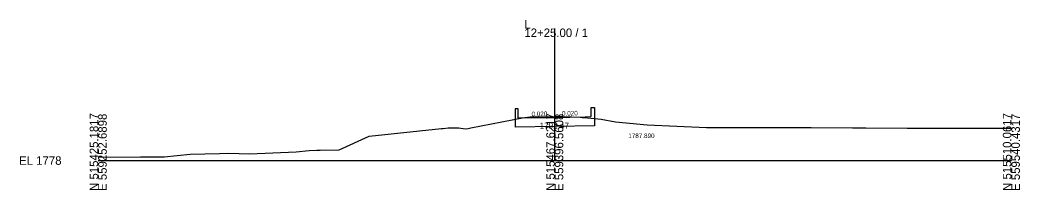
# Model space of a CAD drawing. Extents: x -26 to 1303, y -10 to 9545.
# Drawn here: x -25.7 to 302.8, y 5490.3 to 5546.2 of the extents above; entities that cross this region are included whole.
import ezdxf

# ---------------------------------------------------------------- set-up
doc = ezdxf.new("R2010")
doc.units = 0
for name, color, linetype in [('Exist Cross Section Cell', 7, 'Continuous'), ('Exist XS Center Line Elevation Label', 7, 'Continuous'), ('Exist XS Ground Line', 7, 'Continuous'), ('Prop XS Bridge', 7, 'Continuous'), ('Prop XS Ditch Standard Text', 7, 'Continuous'), ('Prop XS Dump Level', 7, 'Continuous'), ('Prop XS SE Text', 7, 'Continuous')]:
    doc.layers.add(name, color=color, linetype=linetype)

msp = doc.modelspace()

# ---------------------------------------------------------------- linework, layer by layer
at = {"layer": 'Exist Cross Section Cell'}
for p, q in [((150, 5500), (150, 5543.41)), ((0, 5500), (150, 5500)), ((150, 5500), (300, 5500))]:
    msp.add_line(p, q, dxfattribs=at)
at = {"layer": 'Exist XS Ground Line'}
for p, q in [((122.42, 5510.7), (139.4, 5514.06)), ((139.4, 5514.06), (141.92, 5514.35)), ((141.92, 5514.35), (144.73, 5514.41)), ((144.73, 5514.41), (149.88, 5514.47)), ((149.88, 5514.47), (152.79, 5514.43)), ((152.79, 5514.43), (158.3, 5514.26)), ((158.3, 5514.26), (159.04, 5514.2)), ((159.04, 5514.2), (160.77, 5514.05)), ((160.77, 5514.05), (165.22, 5513.56)), ((165.22, 5513.56), (170, 5512.75)), ((89, 5507.99), (112.77, 5510.48)), ((112.77, 5510.48), (113.33, 5510.53)), ((113.33, 5510.53), (114.92, 5510.71)), ((114.92, 5510.71), (118.32, 5510.73)), ((118.32, 5510.73), (120.63, 5510.47)), ((120.63, 5510.47), (121.54, 5510.51)), ((121.54, 5510.51), (122.42, 5510.7)), ((170, 5512.75), (180.31, 5511.73)), ((180.31, 5511.73), (199.83, 5510.84)), ((199.83, 5510.84), (200.75, 5510.82)), ((200.75, 5510.82), (213.2, 5510.83)), ((213.2, 5510.83), (220.12, 5510.85)), ((220.12, 5510.85), (221.52, 5510.81)), ((221.52, 5510.81), (222.79, 5510.85)), ((222.79, 5510.85), (234.28, 5510.85)), ((234.28, 5510.85), (247.81, 5510.7)), ((247.81, 5510.7), (249.66, 5510.7)), ((249.66, 5510.7), (252.14, 5510.71)), ((252.14, 5510.71), (265.76, 5510.63)), ((265.76, 5510.63), (272.28, 5510.59)), ((272.28, 5510.59), (279.68, 5510.61)), ((279.68, 5510.61), (281.56, 5510.62)), ((281.56, 5510.62), (291.23, 5510.64)), ((291.23, 5510.64), (291.62, 5510.65)), ((291.62, 5510.65), (295.42, 5510.67)), ((295.42, 5510.67), (300, 5510.68)), ((79.11, 5503.56), (89, 5507.99)), ((65.03, 5502.89), (69.28, 5503.26)), ((69.28, 5503.26), (71.81, 5503.37)), ((71.81, 5503.37), (72.93, 5503.42)), ((72.93, 5503.42), (79.11, 5503.56)), ((0, 5501.12), (13.92, 5501.19)), ((13.92, 5501.19), (16.04, 5501.21)), ((16.04, 5501.21), (19.56, 5501.24)), ((19.56, 5501.24), (21.62, 5501.26)), ((21.62, 5501.26), (30.21, 5502.12)), ((30.21, 5502.12), (39.88, 5502.32)), ((39.88, 5502.32), (42.97, 5502.41)), ((42.97, 5502.41), (49.7, 5502.15)), ((49.7, 5502.15), (65.03, 5502.89))]:
    msp.add_line(p, q, dxfattribs=at)
at = {"layer": 'Prop XS Bridge'}
for p, q in [((138, 5516.95), (137, 5516.95)), ((137, 5516.95), (137, 5513.95)), ((138, 5513.95), (138, 5516.95)), ((162, 5514.43), (162, 5517.43)), ((162, 5517.43), (163, 5517.43)), ((163, 5517.43), (163, 5514.43)), ((137, 5513.95), (137, 5510.95)), ((140, 5513.99), (138, 5513.95)), ((140, 5513.99), (150, 5514.19)), ((150, 5514.19), (160, 5514.39)), ((160, 5514.39), (162, 5514.43)), ((163, 5514.43), (163, 5511.43)), ((163, 5511.43), (137, 5510.95))]:
    msp.add_line(p, q, dxfattribs=at)

# ---------------------------------------------------------------- texts
at = {"layer": 'Exist Cross Section Cell'}
for s, p in [('L', (140, 5543.41)), ('12+25.00 / 1', (140, 5540.61)), ('EL 1778', (-26, 5498.6))]:
    msp.add_text(s, height=2.8, dxfattribs=at).set_placement(p)
for s, p in [('N 515425.1817', (0, 5490)), ('E 559252.6898', (2.8, 5490)), ('N 515467.6217', (150, 5490)), ('E 559396.5608', (152.8, 5490)), ('N 515510.0617', (300, 5490)), ('E 559540.4317', (302.8, 5490))]:
    msp.add_text(s, height=2.8, rotation=90, dxfattribs=at).set_placement(p)
at = {"layer": 'Exist XS Center Line Elevation Label'}
msp.add_text('1792.47', height=2, dxfattribs=at).set_placement((145.02, 5510.47))
at = {"layer": 'Prop XS Ditch Standard Text'}
msp.add_text('1787.890', height=1.5, dxfattribs=at).set_placement((174.15, 5507.38))
at = {"layer": 'Prop XS Dump Level'}
for s, height, p in [('Case1', 0.04, (137, 5513.71)), ('Eop', 0.3, (130, 5511.9))]:
    msp.add_text(s, height=height, dxfattribs=at).set_placement(p)
at = {"layer": 'Prop XS SE Text'}
for p in [(142.38, 5514.54), (152.38, 5514.74)]:
    msp.add_text('0.020', height=1.5, rotation=1.1458, dxfattribs=at).set_placement(p)

doc.saveas('drawing.dxf')
